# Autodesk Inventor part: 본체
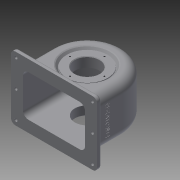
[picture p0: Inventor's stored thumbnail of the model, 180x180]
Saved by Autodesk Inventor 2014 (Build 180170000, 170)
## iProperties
Created: 2015-09
Part Number: 본체
Material: 일반
Document SubType Name: Modeling
Designer: SEC
Density: 1 g/cm^3
Appearance: 기본값
Author: SEC
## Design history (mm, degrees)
sketch "스케치1"
  geometry: L1 (-57, 0)-(-57, -47); L2 (57, 0)-(57, -47); L3 (57, -47)-(-57, -47); A1 r 57 centre (0, 0) between (57, 0) and (-57, 0); 1 further point
  constraints: 6 end point, 2 point on circle, 2 tangent, 1 centre point, 1 coincident, 1 parallel, 1 perpendicular, 1 vertical
  dimensions: "d1" = 47 distance from line of point (0, 0) L3; "d2" = 57 radius of A1
extrude "돌출1" new body sketch "스케치1" distance "d3" = 77; taper "d4" = 0 deg
sketch "스케치4"
  geometry: L1 (57, 77)-(57, 0) reference; L2 (57, 0)-(-47, 0) reference; L3 (-47, 77)-(57, 77) reference; L4 (-47, 0)-(-47, 77) reference; L5 (33, 73.111)-(33, 74); L6 (33, 74)-(20, 74); L7 (20, 74)-(20, 58); L8 (20, 58)-(28, 58); L9 (28, 58)-(39.747, 72); L10 (39.747, 72)-(51, 72); L11 (51, 72)-(51, 5); L12 (51, 5)-(20, 5); L13 (20, 5)-(20, 0); L14 (0, 0)-(0, 77); L15 (37.416, 77)-(0, 77); L16 (37.416, 77)-(33.883, 72.79); A1 r 0.5 centre (33.5, 73.111) between (33, 73.111) and (33.883, 72.79); 1 further point
  constraints: 24 end point, 7 perpendicular, 5 point on line, 2 parallel, 2 point on circle, 2 tangent, 1 centre point, 1 collinear
  dimensions: "d18" = 66 diameter of L5 L14; "d19" = 40 diameter of L7 L14; "d20" = 3 distance between parallel lines of L3 L6; "d21" = 50 deg angle of L8 L9; "d22" = 56 diameter of L8.end L14; "d23" = 16 distance between parallel lines of L8 L6; "d24" = 5 distance between parallel lines of L16 L9; "d25" = 6 distance between parallel lines of L11 L1; "d26" = 5 distance between parallel lines of L3 L10; "d27" = 5 distance between parallel lines of L12 L2; "d28" = 40 diameter of L13 L14; "d134" = 0.5 radius of A1
  node "절단 모서리 투영1"
sketch "스케치5"
  geometry: L1 (57, -47)-(-57, -47) reference; C1 r 31 at (0, 0)
  constraints: 1 centre point
  dimensions: "d29" = 62 diameter of C1; "d30" = 47 distance from line of C1.centre L1
extrude "돌출4" join sketch "스케치5" distance "d31" = 10; taper "d32" = 0 deg
sketch "스케치6"
  geometry: C1 r 31 at (0, 0) reference; C2 r 20 at (0, 0)
  constraints: 1 centre point, 1 coincident
  dimensions: "d34" = 40 diameter of C2
extrude "돌출5" cut sketch "스케치6" distance "d35" = 10; taper "d36" = 0 deg
sketch "스케치7"
  geometry: L1 (-13, 90.5)-(127, 90.5); L2 (127, 90.5)-(127, -13.5); L3 (127, -13.5)-(-13, -13.5); L4 (-13, -13.5)-(-13, 90.5); L5 (0, 0)-(0, 77) reference; L6 (0, 77)-(114, 77) reference; L7 (114, 77)-(114, 0) reference; L8 (114, 0)-(0, 0) reference; L9 (114, 38.5)-(80.915, 38.5); 1 further point
  constraints: 10 end point, 3 parallel, 1 horizontal, 1 midpoint, 1 perpendicular
  dimensions: "d37" = 140 distance of L1.start L1.end; "d38" = 104 distance of L1.end L2.end; "d39" = 70 distance from line of point (57, 0) L2; "d40" = 52 distance between parallel lines of L9 L1
extrude "돌출6" join sketch "스케치7" distance "d41" = 7; taper "d42" = 0 deg
revolve "회전2" stored, may be unused: angle "d43" = 90 deg
node "작업 평면1"
sketch "스케치14"
  geometry: L1 (29, 58)-(85, 58) reference; L2 (29, 58)-(17.253, 72) reference; L3 (85, 58)-(96.747, 72) reference; L4 (108, 72)-(108, 5) reference; L5 (6, 72)-(6, 5) reference; L6 (6, 5)-(108, 5) reference; L7 (6, 72)-(108, 72) reference; 1 further point
extrude "돌출10" cut sketch "스케치14" distance "d64" = 80; taper "d65" = 0 deg
sketch "스케치15"
  geometry: L1 (17.253, 72)-(29, 58) reference; L2 (29, 58)-(85, 58) reference; L3 (85, 58)-(96.747, 72) reference; L4 (127, -13.5)-(127, 90.5) reference; L5 (17.253, 72)-(96.747, 72); 1 further point
  constraints: 2 end point, 1 perpendicular, 1 point on line
extrude "돌출11" cut sketch "스케치15" distance "d67" = 15.5; taper "d68" = 0 deg
sketch "스케치18"
  geometry: L1 (-13, -90.5)-(127, -90.5) reference; L2 (-13, 13.5)-(-13, -90.5) reference; C1 r 2.5 at (-5, -82.5); C2 r 2.5 at (-5, -38.5); C3 r 2.5 at (-5, 5.5); 1 further point
  constraints: 3 centre point
  dimensions: "d69" = 5 diameter of C1; "d70" = 8 distance from line of C1.centre L1; "d71" = 8 distance from line of C1.centre L2; "d72" = 5 diameter of C2; "d73" = 5 diameter of C3; "d74" = 8 distance from line of C2.centre L2; "d75" = 8 distance from line of C3.centre L2; "d76" = 44 distance of C1.centre C2.centre; "d77" = 44 distance of C3.centre C2.centre
extrude "돌출12" cut sketch "스케치18" distance "d78" = 15.5; taper "d79" = 0 deg
node "작업 평면3"
sketch "스케치19"
  geometry: L1 (57, 0)-(57, 77) reference; L2 (57, 77)-(-57, 77) reference; C1 r 6 at (0, 38.5); 1 further point
  constraints: 1 centre point
  dimensions: "d81" = 12 diameter of C1; "d82" = 57 distance from line of C1.centre L1; "d83" = 38.5 distance from line of C1.centre L2
extrude "돌출13" join sketch "스케치19" stored distance "d84" = 15.5; taper "d85" = 10 deg
sketch "스케치20"
  geometry: C1 r 6 at (0, 0) reference; 1 further point
hole "구멍1" sketch "스케치20" at (0, 0) diameter "d86" = 4.459; stored, may be unused: countersink angle "d90" = 90 deg, drill point angle "d92" = 118 deg; dims "d87" = 20, "d88" = 4, "d89" = 2, "d91" = 25
sketch "스케치21"
  geometry: L1 (0, 57)-(0, 0) reference; L2 (90.5, -54)-(-13.5, -54) reference; 1 further point
  constraints: 1 other
  dimensions: "d93" = 38.5 distance from line of point (38.5, -24) L1; "d94" = 30 distance from line of point (38.5, -24) L2
feature "엠보싱1" sketch "스케치21" dims "d1" = 47, "d2" = 57, "d95" = 0.5, "d96" = 0
sketch "스케치22" dims "d97" = 56
  geometry: L1 (0, 0)-(0, 28); C1 r 20 at (0, 0) reference
  constraints: 2 end point, 1 coincident, 1 vertical, 1 vertical alignment, 2 other
hole "구멍2" sketch "스케치22" at (0, 28) diameter "d98" = 2.459; stored, may be unused: countersink angle "d102" = 90 deg, drill point angle "d104" = 118 deg; dims "d99" = 7, "d100" = 4, "d101" = 2, "d103" = 9
sketch "스케치23" dims "d108" = 48
  geometry: L1 (0, 0)-(0, 24); C1 r 31 at (0, 0) reference
  constraints: 2 end point, 1 coincident, 1 vertical, 1 vertical alignment, 2 other
hole "구멍3" sketch "스케치23" at (0, 24) diameter "d109" = 2.459; stored, may be unused: countersink angle "d113" = 90 deg, drill point angle "d115" = 118 deg; dims "d110" = 6, "d111" = 4, "d112" = 2, "d114" = 8
fillet "모깎기1" dims "d119" = 3
fillet "모깎기2" dims "d120" = 14
sketch "스케치24"
  geometry: L1 (6, 72)-(108, 72) reference; L2 (108, 72)-(108, 5) reference; L3 (108, 5)-(6, 5) reference; L4 (6.483, 72)-(6.483, 5) reference; L5 (107.517, 5)-(107.517, 72) reference; 1 further point
extrude "돌출14" join sketch "스케치24" distance "d121" = 60; taper "d122" = 0 deg
sketch "스케치25"
  geometry: L1 (6, 72)-(107.517, 72) reference; L2 (107.517, 5)-(6, 5) reference; L3 (6, 5)-(6, 72) reference; L4 (6.483, 72)-(6.483, 5) reference; 1 further point
extrude "돌출15" join sketch "스케치25" distance "d123" = 60; taper "d124" = 0 deg
fillet "모깎기3" dims "d125" = 9
fillet "모깎기4" dims "d126" = 9
fillet "모깎기5" dims "d127" = 9
fillet "모깎기6" dims "d128" = 7
fillet "모깎기7" dims "d129" = 3
chamfer "모따기1" distance "d130" = 1; stored, may be unused: second distance "d131" = 2, angle "d132" = 45 deg
fillet "모깎기8" dims "d133" = 1
node "솔리드1"
mirror "대칭1"
pattern_circular "원형 패턴1" dims angle "d106" = 360 deg
pattern_circular "원형 패턴2" dims angle "d117" = 360 deg
node "절단 모서리 투영2"
other parameters: "d0" = 114, "d63" = -47
